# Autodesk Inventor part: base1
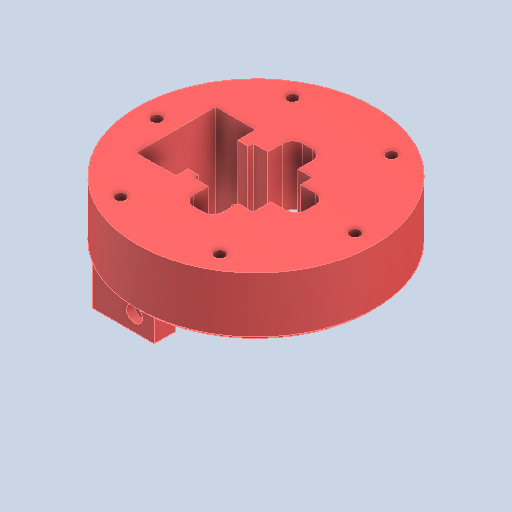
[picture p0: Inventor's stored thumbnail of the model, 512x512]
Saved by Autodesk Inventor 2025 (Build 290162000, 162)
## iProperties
Created: 2025-11
Part Number: base1
Material: Plastica ABS
Document SubType Name: Modeling
Designer: Ryzen5700u
Density: 1.06 g/cm^3
Appearance: Default
Author: Ryzen5700u
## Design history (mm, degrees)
feature "Solido1"
node "Solido2"
